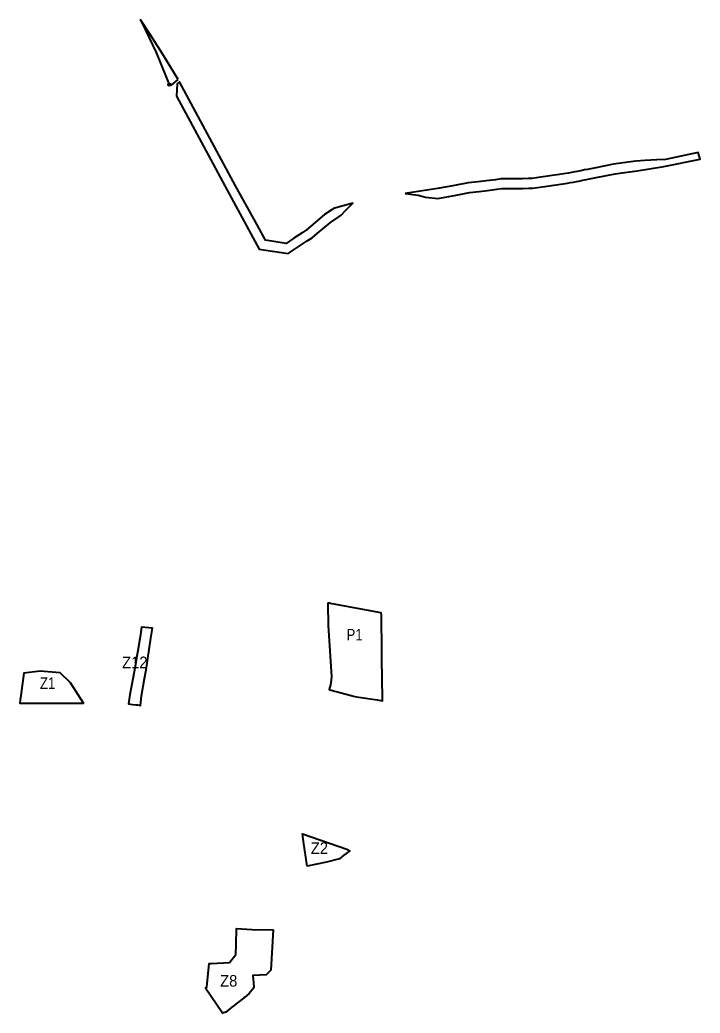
# Model space of a CAD drawing. Extents: x -555426 to -553131, y -1186725 to -1183160.
# Drawn here: x -554609 to -553554, y -1184702 to -1183160 of the extents above; entities that cross this region are included whole.
import ezdxf
from ezdxf.enums import TextEntityAlignment as Align

# ---------------------------------------------------------------- set-up
doc = ezdxf.new("R2010")
doc.units = 0
doc.header["$LTSCALE"] = 7.2
doc.header["$PDMODE"] = 32
doc.header["$PDSIZE"] = 3.6
for name, color, linetype, lineweight in [('12', 7, 'Continuous', 40), ('2', 7, 'Continuous', 40), ('4', 7, 'Continuous', 40), ('48', 7, 'Continuous', 40), ('62', 7, 'Continuous', 25), ('8', 7, 'Continuous', 40)]:
    doc.layers.add(name, color=color, linetype=linetype, lineweight=lineweight)
doc.layers.add('60', color=7, linetype='Continuous')
doc.layers.add('61', color=7, linetype='Continuous')

msp = doc.modelspace()

# ---------------------------------------------------------------- linework, layer by layer
at = {"layer": '12'}
msp.add_lwpolyline([(-554216.082, -1184572.657), (-554219.51, -1184635.3), (-554226.98, -1184642.35), (-554247.47, -1184643.35), (-554246.78, -1184649.63), (-554246.31, -1184654.17), (-554245.93, -1184662.76), (-554253.15, -1184671.5), (-554260.66, -1184677.77), (-554261.49, -1184678.42), (-554267.01, -1184682.66), (-554273.25, -1184687.46), (-554276.41, -1184689.96), (-554280.002, -1184692.844), (-554289.4, -1184700.39), (-554294.55, -1184701.98), (-554321.096, -1184663.282), (-554318.775, -1184661.419), (-554315.201, -1184624.889), (-554312.325, -1184624.733), (-554283.78, -1184623.18), (-554273.897, -1184610.896), (-554273.46, -1184595.6), (-554272.744, -1184570.534), (-554248.927, -1184572.119)], close=True, dxfattribs=at)
at = {"layer": '2'}
for points in [[(-554535.41, -1184220.79), (-554526.4, -1184220.82), (-554519.59, -1184220.81), (-554509.93, -1184220.84), (-554530.2, -1184189.32), (-554546.63, -1184173.61), (-554577.52, -1184171.17), (-554602.96, -1184174.54), (-554607.39, -1184209.02), (-554608.27, -1184215.84), (-554608.89, -1184220.71), (-554597.59, -1184220.73), (-554570.19, -1184220.76)], [(-554570.19, -1184220.76), (-554559.89, -1184220.77), (-554535.41, -1184220.79)]]:
    msp.add_lwpolyline(points, dxfattribs=at)
msp.add_lwpolyline([(-554163.2, -1184474.11), (-554169.02, -1184435.57), (-554170.7, -1184423.54), (-554101.44, -1184447.55), (-554096.79, -1184449.95), (-554106.24, -1184456.86), (-554113.17, -1184462.37), (-554133.03, -1184467.75)], close=True, dxfattribs=at)
at = {"layer": '4'}
msp.add_lwpolyline([(-554054.44, -1184215.95), (-554046.46, -1184217.21), (-554046.49, -1184214.37), (-554047.25, -1184151.79), (-554047.37, -1184141.38), (-554048.13, -1184084.31), (-554048.18, -1184080.56), (-554051.69, -1184079.91), (-554127.06, -1184066.03), (-554130.79, -1184065.34), (-554130.94, -1184066.61), (-554130.56, -1184100.41), (-554125.32, -1184179.55), (-554126.18, -1184185.43), (-554127.18, -1184192.25), (-554129.31, -1184199.7), (-554120.6, -1184202.17), (-554115.94, -1184203.49), (-554091.23, -1184210.19), (-554086.75, -1184210.89)], close=True, dxfattribs=at)
at = {"layer": '48'}
msp.add_line((-553665.24, -1183381.36), (-553676.67, -1183382.9), dxfattribs=at)
for points in [[(-554363.18, -1183253.13), (-554387.431, -1183213.215), (-554406.75, -1183182.832), (-554421.72, -1183160.34), (-554414.65, -1183175.07), (-554397.33, -1183211.12), (-554377.12, -1183260.83)], [(-554377.12, -1183260.83), (-554373.37, -1183261.05), (-554363.18, -1183253.13)], [(-554110.58, -1183463.31), (-554103.48, -1183456.27), (-554092.27, -1183445.06), (-554122.231, -1183453.201), (-554124.207, -1183454.614), (-554136.184, -1183462.634), (-554157.583, -1183480.555), (-554164.408, -1183486.48), (-554171.218, -1183490.925), (-554184.025, -1183499.312), (-554196.042, -1183507.394), (-554228.053, -1183502.414), (-554240.95, -1183478.721), (-554274.264, -1183417.699), (-554310.485, -1183350.454), (-554361.077, -1183256.605), (-554365.04, -1183259.86), (-554366.04, -1183279.01), (-554323.69, -1183357.57), (-554287.45, -1183424.85), (-554254.12, -1183485.9)], [(-553943.503, -1183434.312), (-553932.051, -1183432.172), (-553911.142, -1183428.372), (-553896.168, -1183426.715), (-553883.573, -1183425.111), (-553869.084, -1183423.282), (-553861.405, -1183422.316), (-553853.741, -1183422.198), (-553845.312, -1183422.059), (-553837.037, -1183421.999), (-553828.747, -1183421.868), (-553820.02, -1183421.688), (-553813.001, -1183421.608), (-553802.104, -1183420.04), (-553791.062, -1183418.375), (-553780.765, -1183416.848), (-553769.471, -1183415.181), (-553759.583, -1183413.737), (-553754.87, -1183412.847), (-553750.223, -1183412.031), (-553745.572, -1183411.128), (-553741.554, -1183410.472), (-553735.462, -1183409.258), (-553729.823, -1183408.041), (-553725.417, -1183407.201), (-553720.004, -1183406.234), (-553715.047, -1183405.105), (-553685.3, -1183399.258), (-553674.627, -1183397.76), (-553663.208, -1183396.222), (-553651.335, -1183394.575), (-553609.73, -1183387.865), (-553553.598, -1183376.687), (-553556.6, -1183365.96), (-553607.36, -1183376.83), (-553620.62, -1183377.81), (-553629.85, -1183378.3), (-553639.56, -1183378.81), (-553653.56, -1183379.74), (-553665.24, -1183381.36)], [(-553676.67, -1183382.9), (-553687.79, -1183384.46), (-553718.16, -1183390.43), (-553722.99, -1183391.53), (-553728.14, -1183392.45), (-553732.81, -1183393.34), (-553738.51, -1183394.57), (-553744.23, -1183395.71), (-553748.21, -1183396.36), (-553752.95, -1183397.28), (-553757.56, -1183398.09), (-553762.06, -1183398.94), (-553771.65, -1183400.34), (-553782.96, -1183402.01), (-553793.28, -1183403.54), (-553804.29, -1183405.2), (-553814.16, -1183406.62), (-553820.26, -1183406.69)], [(-553820.26, -1183406.69), (-553829.02, -1183406.87), (-553837.21, -1183407), (-553845.49, -1183407.06), (-553853.98, -1183407.2), (-553862.46, -1183407.33), (-553870.96, -1183408.4), (-553885.46, -1183410.23), (-553897.94, -1183411.82), (-553913.31, -1183413.52)], [(-553913.31, -1183413.52), (-553934.77, -1183417.42), (-553946.22, -1183419.56), (-553961.04, -1183422.25), (-554011.181, -1183429.704)], [(-554011.181, -1183429.704), (-553990.975, -1183432.278), (-553979.461, -1183435.498), (-553960.428, -1183437.384), (-553943.503, -1183434.312)], [(-554254.12, -1183485.9), (-554254.12, -1183485.9), (-554237.684, -1183516.096), (-554192.544, -1183523.119), (-554175.73, -1183511.81), (-554163.01, -1183503.48), (-554155.35, -1183498.48), (-554147.85, -1183491.97), (-554127.17, -1183474.65), (-554115.67, -1183466.95), (-554110.58, -1183463.31)]]:
    msp.add_lwpolyline(points, dxfattribs=at)
msp.add_point((-554377.12, -1183260.83), dxfattribs=at)
at = {"layer": '62'}
for points in [[(-554054.44, -1184215.95), (-554046.46, -1184217.21), (-554046.49, -1184214.37), (-554047.25, -1184151.79), (-554047.37, -1184141.38), (-554048.18, -1184080.56), (-554051.69, -1184079.91), (-554127.06, -1184066.03), (-554130.79, -1184065.34), (-554130.94, -1184066.61), (-554130.56, -1184100.41), (-554125.32, -1184179.55), (-554126.18, -1184185.43), (-554127.18, -1184192.25), (-554129.31, -1184199.7), (-554115.94, -1184203.49), (-554091.23, -1184210.19), (-554086.75, -1184210.89), (-554052.356, -1184216.276)], [(-554415.38, -1184182.72), (-554413.02, -1184168.92), (-554405.62, -1184120.08), (-554403.37, -1184104.58), (-554420.12, -1184103.06), (-554422.41, -1184117.71), (-554430.77, -1184166.73), (-554433.24, -1184180.51), (-554438.09, -1184207.49), (-554440.16, -1184222.12), (-554434.03, -1184222.84), (-554428.6, -1184223.48), (-554426.63, -1184223.71), (-554421.69, -1184224.28), (-554419.97, -1184209.57), (-554414.982, -1184180.391)], [(-554216.082, -1184572.657), (-554219.51, -1184635.3), (-554226.98, -1184642.35), (-554247.47, -1184643.35), (-554246.78, -1184649.63), (-554246.31, -1184654.17), (-554245.93, -1184662.76), (-554253.15, -1184671.5), (-554260.66, -1184677.77), (-554261.49, -1184678.42), (-554267.01, -1184682.66), (-554273.25, -1184687.46), (-554276.41, -1184689.96), (-554280.002, -1184692.844), (-554289.4, -1184700.39), (-554294.55, -1184701.98), (-554321.096, -1184663.282), (-554318.775, -1184661.419), (-554315.201, -1184624.889), (-554312.325, -1184624.733), (-554283.78, -1184623.18), (-554273.897, -1184610.896), (-554273.46, -1184595.6), (-554272.744, -1184570.534), (-554248.927, -1184572.119), (-554215.254, -1184572.671)]]:
    msp.add_lwpolyline(points, dxfattribs=at)
for points in [[(-554535.41, -1184220.79), (-554559.89, -1184220.77), (-554570.19, -1184220.76), (-554597.59, -1184220.73), (-554608.89, -1184220.71), (-554608.27, -1184215.84), (-554607.39, -1184209.02), (-554602.96, -1184174.54), (-554577.52, -1184171.17), (-554546.63, -1184173.61), (-554530.2, -1184189.32), (-554509.93, -1184220.84), (-554519.59, -1184220.81), (-554526.4, -1184220.82)], [(-554163.2, -1184474.11), (-554169.02, -1184435.57), (-554170.7, -1184423.54), (-554101.44, -1184447.55), (-554096.79, -1184449.95), (-554106.24, -1184456.86), (-554113.17, -1184462.37), (-554133.03, -1184467.75)]]:
    msp.add_lwpolyline(points, close=True, dxfattribs=at)
at = {"layer": '8'}
msp.add_lwpolyline([(-554415.38, -1184182.72), (-554413.02, -1184168.92), (-554405.62, -1184120.08), (-554403.37, -1184104.58), (-554420.12, -1184103.06), (-554422.41, -1184117.71), (-554430.77, -1184166.73), (-554433.24, -1184180.51), (-554438.09, -1184207.49), (-554440.16, -1184222.12), (-554434.03, -1184222.84), (-554428.6, -1184223.48), (-554426.63, -1184223.71), (-554421.69, -1184224.28), (-554419.97, -1184209.57)], close=True, dxfattribs=at)

# ---------------------------------------------------------------- texts
at = {"layer": '60'}
for s, width, p in [('Z12', 0.95, (-554430.61, -1184166.562)), ('Z1', 0.85, (-554565.936, -1184198.924)), ('Z2', 0.95, (-554144.174, -1184454.791)), ('Z8', 0.95, (-554284.883, -1184660.842))]:
    msp.add_text(s, height=18, dxfattribs=dict(at, width=width)).set_placement(p, align=Align.CENTER)
at = {"layer": '61', "width": 0.85}
msp.add_text('P1', height=18, dxfattribs=at).set_placement((-554089.634, -1184123.529), align=Align.CENTER)

doc.saveas('drawing.dxf')
